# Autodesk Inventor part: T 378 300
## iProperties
Company: Mayer & Müller AG Schaltgeräte
Created: 2005-12
Part Number: T 378 300
Material: Umabord KE
Document SubType Name: Modeling
Designer: I.Baliuc
Manufacturer: Standard
Standards Organization: Custom
Description: Isolierplatte
Density: 1.4 g/cm^3
HalbzeugNorm: RAL 7035
Zweck: als Vorkontaktstütze
Abmessung: 15 mm dick
Author: T.Messerschmitt
Revision Number: 378300
Comments: Bemassung d. Bohrung geändert von 10,2 auf 11,45 mm 14.06.06 - Baliuc
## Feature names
1. Extrusion2
2. Bohrung_Ø8.4 [Hole]
3. Fase1 [Chamfer]
4. Bohrung2 [Hole]
